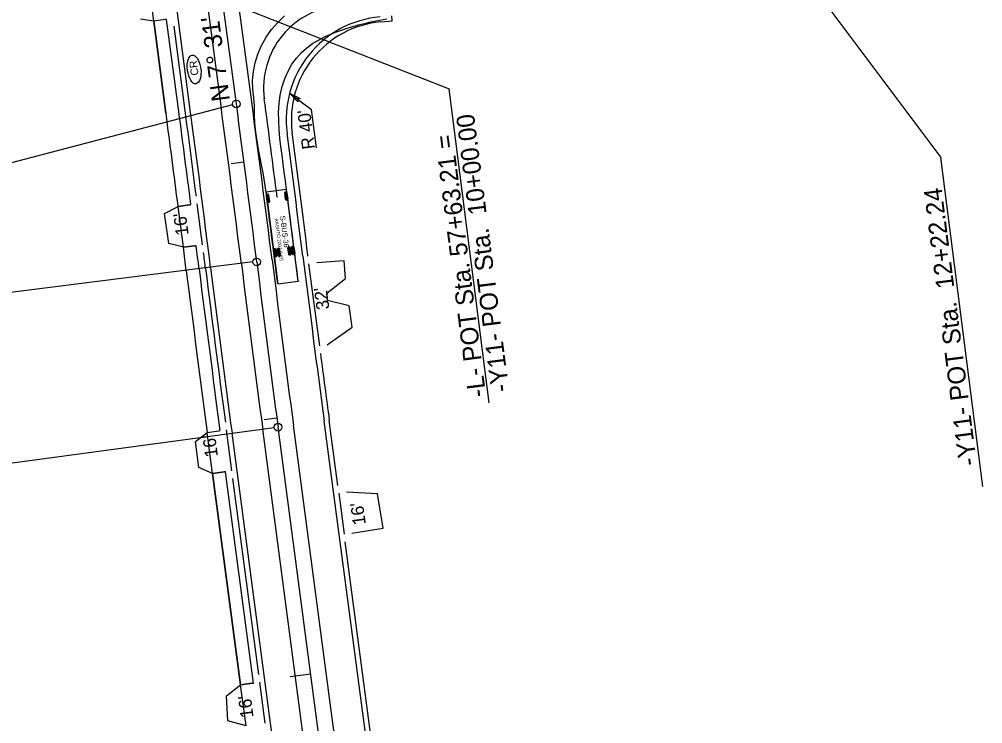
# Model space of a CAD drawing. Extents: x 2367848 to 2369479, y 800728 to 808616.
# Drawn here: x 2368547.1 to 2368920.4, y 805799.6 to 806072.5 of the extents above; entities that cross this region are included whole.
import ezdxf

# ---------------------------------------------------------------- set-up
doc = ezdxf.new("R2010")
doc.units = 0
for name, color, linetype in [('Prop AutoTurn Projected Path', 7, 'Continuous'), ('Prop AutoTurn Simulation', 7, 'Continuous'), ('Prop Conc 2ft 6in Curb and Gutter', 7, 'Continuous'), ('Prop Conc 4in Sidewalk', 7, 'Continuous'), ('Prop Conc Drive Radius Type', 7, 'Continuous'), ('Prop Conc Driveway', 7, 'Continuous'), ('Prop Dimension', 7, 'Continuous'), ('Prop EOT', 7, 'Continuous'), ('Prop Horizontal Alignment', 7, 'Continuous'), ('Prop Horizontal Alignment Direction Label', 7, 'Continuous'), ('Prop Horizontal Alignment Station Label', 7, 'Continuous'), ('Prop Horizontal Alignment Tick Large', 7, 'Continuous'), ('Prop Horizontal Alignment Tick Small', 7, 'Continuous'), ('Prop Lane Lines', 7, 'Continuous'), ('Prop Shade Light', 7, 'Continuous'), ('Prop Terminator CELL', 7, 'Continuous'), ('Prop WCC CELL', 7, 'Continuous'), ('Prop WCR CELL', 7, 'Continuous')]:
    doc.layers.add(name, color=color, linetype=linetype)

# ---------------------------------------------------------------- blocks, each defined once
blk = doc.blocks.new('CR')
at = {"layer": 'Prop WCC CELL'}
blk.add_ellipse((0.02, -0.02), major_axis=(5.61, 0), ratio=0.462467, dxfattribs=at)
blk.add_text('CR', height=3, dxfattribs=at).set_placement((-2.34, -1.5))

msp = doc.modelspace()

# ---------------------------------------------------------------- linework, layer by layer
at = {"layer": 'Prop AutoTurn Projected Path'}
for centre, radius, start, end in [((2368673.73, 806045.93), 32, 93.7494, 187.5296), ((2358717.33, 804729.9), 10011, 7.309596, 7.529629)]:
    msp.add_arc(centre, radius, start, end, dxfattribs=at)
at = {"layer": 'Prop AutoTurn Simulation'}
for p, q in [((2368650.62, 806006.6), (2368642.68, 806005.58)), ((2368642.68, 806005.58), (2368647.24, 805970.07)), ((2368642.68, 806005.58), (2368642.68, 806005.58)), ((2368642.99, 806004.78), (2368643.42, 806001.47)), ((2368643.2, 806004.81), (2368643.63, 806001.5)), ((2368643.41, 806004.83), (2368643.83, 806001.53)), ((2368650.1, 806005.69), (2368650.53, 806002.39)), ((2368650.31, 806005.72), (2368650.73, 806002.41)), ((2368650.52, 806005.75), (2368650.94, 806002.44)), ((2368655.17, 805971.09), (2368650.62, 806006.6)), ((2368645.7, 805983.65), (2368646.13, 805980.35)), ((2368645.91, 805983.68), (2368646.34, 805980.37)), ((2368646.12, 805983.71), (2368646.54, 805980.4)), ((2368647.19, 805983.84), (2368647.62, 805980.54)), ((2368647.4, 805983.87), (2368647.82, 805980.56)), ((2368647.61, 805983.9), (2368648.03, 805980.59)), ((2368651.33, 805984.37), (2368651.75, 805981.07)), ((2368651.53, 805984.4), (2368651.96, 805981.09)), ((2368651.74, 805984.43), (2368652.16, 805981.12)), ((2368652.81, 805984.57), (2368653.24, 805981.26)), ((2368653.02, 805984.59), (2368653.44, 805981.29)), ((2368653.23, 805984.62), (2368653.65, 805981.31)), ((2368647.24, 805970.07), (2368655.17, 805971.09))]:
    msp.add_line(p, q, dxfattribs=at)
for points in [[(2368647.24, 805970.07), (2368646.78, 805973.62), (2368646.33, 805977.17), (2368645.87, 805980.72), (2368645.41, 805984.28), (2368644.96, 805987.83), (2368644.5, 805991.38), (2368644.05, 805994.93), (2368643.59, 805998.48), (2368643.13, 806002.03), (2368642.67, 806005.58), (2368642.67, 806005.58), (2368642.24, 806008.89), (2368641.71, 806012.2), (2368641.1, 806015.49), (2368640.43, 806018.79), (2368639.78, 806022.11), (2368639.19, 806025.46), (2368638.71, 806028.82), (2368638.36, 806032.2), (2368638.18, 806035.54), (2368638.15, 806038.79), (2368637.93, 806042.04), (2368637.54, 806045.36), (2368637.48, 806048.76), (2368637.79, 806052.2), (2368638.48, 806055.64), (2368639.53, 806059.03), (2368640.95, 806062.33), (2368642.7, 806065.5), (2368644.79, 806068.5), (2368647.18, 806071.28), (2368649.86, 806073.83)], [(2368678.18, 806070.23), (2368679.08, 806070.47), (2368680.22, 806070.75), (2368681.41, 806071.04), (2368682.65, 806071.32), (2368683.93, 806071.6), (2368685.26, 806071.87), (2368686.62, 806072.15), (2368688.01, 806072.41), (2368689.43, 806072.67)], [(2368655.17, 805971.09), (2368654.72, 805974.64), (2368654.26, 805978.19), (2368653.81, 805981.74), (2368653.35, 805985.29), (2368652.9, 805988.84), (2368652.44, 805992.4), (2368651.99, 805995.95), (2368651.53, 805999.5), (2368651.07, 806003.05), (2368650.62, 806006.6), (2368650.62, 806006.6), (2368650.62, 806006.6), (2368650.19, 806009.91), (2368649.76, 806013.23), (2368649.34, 806016.55), (2368648.91, 806019.86), (2368648.47, 806023.18), (2368648.06, 806026.5), (2368647.75, 806029.82), (2368647.57, 806033.16), (2368647.55, 806036.51), (2368647.75, 806039.84), (2368648.2, 806043.15), (2368648.93, 806046.4), (2368649.93, 806049.5), (2368651.2, 806052.4), (2368652.73, 806055.07), (2368654.47, 806057.49), (2368656.41, 806059.63), (2368658.51, 806061.49), (2368660.73, 806063.09), (2368663.01, 806064.46), (2368665.32, 806065.66), (2368667.64, 806066.71), (2368669.95, 806067.64), (2368672.26, 806068.46), (2368674.55, 806069.2), (2368676.82, 806069.87), (2368678.18, 806070.23)]]:
    msp.add_lwpolyline(points, dxfattribs=at)
for points in [[(2368642.94, 806004.77), (2368643.46, 806004.84), (2368643.67, 806004.4), (2368643.98, 806002.02), (2368643.88, 806001.53), (2368643.37, 806001.47), (2368643.15, 806001.91), (2368642.85, 806004.29)], [(2368650.05, 806005.69), (2368650.57, 806005.75), (2368650.78, 806005.31), (2368651.09, 806002.93), (2368650.99, 806002.45), (2368650.48, 806002.38), (2368650.26, 806002.82), (2368649.96, 806005.2)], [(2368645.65, 805983.65), (2368646.17, 805983.71), (2368646.38, 805983.27), (2368646.69, 805980.89), (2368646.59, 805980.41), (2368646.08, 805980.34), (2368645.86, 805980.78), (2368645.56, 805983.16)], [(2368647.14, 805983.84), (2368647.66, 805983.9), (2368647.87, 805983.46), (2368648.18, 805981.08), (2368648.08, 805980.6), (2368647.57, 805980.53), (2368647.35, 805980.97), (2368647.05, 805983.35)], [(2368651.27, 805984.37), (2368651.79, 805984.43), (2368652, 805983.99), (2368652.31, 805981.61), (2368652.21, 805981.13), (2368651.7, 805981.06), (2368651.48, 805981.5), (2368651.18, 805983.89)], [(2368652.76, 805984.56), (2368653.28, 805984.62), (2368653.49, 805984.18), (2368653.8, 805981.8), (2368653.7, 805981.32), (2368653.19, 805981.25), (2368652.97, 805981.7), (2368652.67, 805984.08)]]:
    msp.add_lwpolyline(points, close=True, dxfattribs=at)
for centre in [(2368678.18, 806070.23), (2368678.18, 806070.23), (2368642, 806041.73), (2368642, 806041.73), (2368646.97, 806003.61), (2368655.17, 805971.09), (2368647.24, 805970.07)]:
    msp.add_circle(centre, 0.0417, dxfattribs=at)
at = {"layer": 'Prop Conc 2ft 6in Curb and Gutter'}
for p, q in [((2368687.09, 806071.46), (2368691.58, 806071.86)), ((2368691.58, 806071.86), (2368691.4, 806073.85)), ((2368611.35, 806037.09), (2368607.03, 806069.78)), ((2368670.51, 805891.85), (2368667.16, 805917.13)), ((2368639.85, 805818.64), (2368629.79, 805894.61)), ((2368758.08, 805230.44), (2368673.39, 805870.04))]:
    msp.add_line(p, q, dxfattribs=at)
for centre, radius, start, end in [((2368690.47, 806033.61), 38, 95.1122, 187.4476), ((2358717.33, 804729.9), 9980, 7.334525, 7.526261), ((2358717.33, 804729.9), 10020, 7.172685, 7.447577), ((2358717.33, 804729.9), 9980, 7.172685, 7.208222), ((2378560.81, 807227.11), 9980, 187.172674, 187.174058), ((2378560.81, 807227.11), 10020, 187.172674, 187.516225), ((2378560.81, 807227.11), 9980, 187.392226, 187.5424)]:
    msp.add_arc(centre, radius, start, end, dxfattribs=at)
at = {"layer": 'Prop Conc 4in Sidewalk'}
for p, q in [((2368603.91, 806036.11), (2368599.2, 806071.79)), ((2368608.87, 806036.76), (2368604.16, 806072.39)), ((2368632.81, 805814.69), (2368621.96, 805896.6)), ((2368637.76, 805815.38), (2368626.93, 805897.21))]:
    msp.add_line(p, q, dxfattribs=at)
for centre, radius, start, end in [((2368604.04, 806069.38), 3.01, 87.6915, 97.1618), ((2358717.33, 804729.9), 9972.5, 7.317252, 7.526261), ((2358717.33, 804729.9), 9977.5, 7.317563, 7.526261), ((2368612.65, 806003.58), 3, 277.4213, 287.6804), ((2358717.33, 804729.9), 9972.5, 7.172685, 7.225325), ((2368615.47, 805981.75), 3.01, 87.5484, 97.1646), ((2358717.33, 804729.9), 9977.5, 7.172685, 7.225151), ((2378560.81, 807227.11), 10027.5, 187.172674, 187.533386), ((2378560.81, 807227.11), 10022.5, 187.172674, 187.533139), ((2368623.93, 805916.03), 3, 277.5824, 287.1694), ((2368626.81, 805894.2), 3.01, 87.757, 97.321), ((2368636.87, 805818.25), 3, 277.5806, 287.1623)]:
    msp.add_arc(centre, radius, start, end, dxfattribs=at)
at = {"layer": 'Prop Conc Drive Radius Type'}
for p, q in [((2368618.07, 805985.13), (2368616.01, 806000.99)), ((2368659.18, 805977.77), (2368663.38, 805946.04)), ((2368629.4, 805897.58), (2368627.3, 805913.45)), ((2368670.9, 805888.88), (2368673, 805873.02)), ((2368642.35, 805799.81), (2368640.24, 805815.67))]:
    msp.add_line(p, q, dxfattribs=at)
at = {"layer": 'Prop Conc Driveway'}
for p, q in [((2368599.2, 806071.79), (2368597.15, 806087.66)), ((2368599.2, 806071.79), (2368594.06, 806072.59)), ((2368603.66, 806072.37), (2368599.2, 806071.79)), ((2368603.39, 805997.3), (2368608.58, 806000.03)), ((2368613.04, 806000.61), (2368608.58, 806000.03)), ((2368610.63, 805984.16), (2368608.58, 806000.03)), ((2368604.97, 805985.64), (2368603.39, 805997.3)), ((2368610.63, 805984.16), (2368604.97, 805985.64)), ((2368610.63, 805984.16), (2368615.1, 805984.74)), ((2368615.29, 805908.91), (2368619.86, 805912.46)), ((2368619.86, 805912.46), (2368624.32, 805913.05)), ((2368621.96, 805896.6), (2368619.86, 805912.46)), ((2368616.62, 805898.89), (2368615.29, 805908.91)), ((2368621.96, 805896.6), (2368616.62, 805898.89)), ((2368621.96, 805896.6), (2368626.42, 805897.19)), ((2368637.27, 805815.28), (2368632.81, 805814.69)), ((2368634.91, 805798.82), (2368632.81, 805814.69))]:
    msp.add_line(p, q, dxfattribs=at)
at = {"layer": 'Prop Dimension'}
for p in [(2368651.81, 806043.85), (2368662.24, 806022.67)]:
    msp.add_line(p, (2368660.31, 806037.55), dxfattribs=at)
at = {"layer": 'Prop EOT'}
for p, q in [((2368613.33, 806037.35), (2368557.45, 806460.31)), ((2368672.98, 805978.96), (2368662.3, 805978.13)), ((2368673.45, 805972.08), (2368672.98, 805978.96)), ((2368666.17, 805966.34), (2368673.45, 805972.08)), ((2368666.51, 805963.59), (2368666.17, 805966.34)), ((2368674.9, 805961.48), (2368666.51, 805963.59)), ((2368676.06, 805953.17), (2368674.9, 805961.48)), ((2368666.35, 805946.44), (2368676.06, 805953.17)), ((2368756.1, 805230.18), (2368665.18, 805916.87)), ((2368664.15, 805650.39), (2368629.49, 805912.14)), ((2368685.82, 805888.62), (2368673.87, 805889.27)), ((2368688.02, 805875.33), (2368685.82, 805888.62)), ((2368675.97, 805873.41), (2368688.02, 805875.33)), ((2368627.29, 805810.38), (2368632.81, 805814.69)), ((2368627.86, 805800.77), (2368627.29, 805810.38)), ((2368634.91, 805798.82), (2368627.86, 805800.77))]:
    msp.add_line(p, q, dxfattribs=at)
for centre, radius, start, end in [((2368690.47, 806033.61), 40, 95.1122, 187.4476), ((2358717.33, 804729.9), 9982, 7.172685, 7.526261), ((2358717.33, 804729.9), 10018, 7.172685, 7.447577), ((2378560.81, 807227.11), 9982, 187.172674, 187.5424), ((2378560.81, 807227.11), 10018, 187.172674, 187.5424)]:
    msp.add_arc(centre, radius, start, end, dxfattribs=at)
at = {"layer": 'Prop Horizontal Alignment'}
for p, q in [((2368631.17, 806039.71), (2368556.15, 806607.59)), ((2368753.14, 805115.37), (2368647.33, 805914.51))]:
    msp.add_line(p, q, dxfattribs=at)
for centre, start, end in [((2358717.33, 804729.9), 7.172685, 7.526261), ((2378560.81, 807227.11), 187.172674, 187.5424)]:
    msp.add_arc(centre, 10000, start, end, dxfattribs=at)
at = {"layer": 'Prop Horizontal Alignment Station Label'}
for p, q in [((2368847.64, 806094.4), (2368904.1, 806018.96)), ((2368625.87, 806079.87), (2368713.66, 806045.49)), ((2368729.19, 805923.89), (2368713.66, 806045.49)), ((2368629.72, 806039.33), (2368362.9, 805969.6)), ((2368920.38, 805891.52), (2368904.1, 806018.96)), ((2368637.57, 805978.51), (2368390.31, 805947.21)), ((2368645.82, 805914.28), (2368424.55, 805884.43))]:
    msp.add_line(p, q, dxfattribs=at)
for centre in [(2368631.17, 806039.71), (2368631.17, 806039.71), (2368639.07, 805978.51), (2368639.07, 805978.51), (2368647.33, 805914.51), (2368647.33, 805914.51)]:
    msp.add_circle(centre, 1.5, dxfattribs=at)
at = {"layer": 'Prop Horizontal Alignment Tick Large'}
msp.add_line((2368659.99, 805818.88), (2368652.06, 805817.83), dxfattribs=at)
msp.add_line((2368659.99, 805818.88), (2368652.06, 805817.83), dxfattribs=at)
at = {"layer": 'Prop Horizontal Alignment Tick Small'}
for p, q in [((2368634.12, 806017.2), (2368629.16, 806016.56)), ((2368634.12, 806017.2), (2368629.16, 806016.56)), ((2368646.87, 805918.02), (2368641.91, 805917.36)), ((2368646.87, 805918.02), (2368641.91, 805917.36))]:
    msp.add_line(p, q, dxfattribs=at)
at = {"layer": 'Prop Lane Lines'}
for p, q in [((2368625.23, 806038.92), (2368550.2, 806606.8)), ((2368637.12, 806040.49), (2368562.1, 806608.37)), ((2368759.09, 805116.16), (2368653.28, 805915.29)), ((2368747.19, 805114.58), (2368641.38, 805913.72))]:
    msp.add_line(p, q, dxfattribs=at)
for centre, radius, start, end in [((2358717.33, 804729.9), 9994, 7.172685, 7.526261), ((2358717.33, 804729.9), 10006, 7.172685, 7.526261), ((2378560.81, 807227.11), 10006, 187.172674, 187.5424), ((2378560.81, 807227.11), 9994, 187.172674, 187.5424)]:
    msp.add_arc(centre, radius, start, end, dxfattribs=at)
at = {"layer": 'Prop Shade Light'}
for p, q in [((2368603.66, 806072.37), (2368599.2, 806071.79)), ((2368599.2, 806071.79), (2368603.91, 806036.11)), ((2368608.87, 806036.76), (2368604.16, 806072.39)), ((2368608.61, 806000.03), (2368613.04, 806000.61)), ((2368615.1, 805984.74), (2368610.64, 805984.16)), ((2368619.86, 805912.46), (2368624.32, 805913.05)), ((2368626.42, 805897.19), (2368621.96, 805896.6)), ((2368621.96, 805896.6), (2368632.81, 805814.69)), ((2368637.76, 805815.38), (2368626.93, 805897.21)), ((2368632.81, 805814.69), (2368637.27, 805815.28))]:
    msp.add_line(p, q, dxfattribs=at)
for centre, radius, start, end in [((2368604.04, 806069.38), 3.01, 87.6915, 97.1618), ((2358717.33, 804729.9), 9972.5, 7.317252, 7.526261), ((2358717.33, 804729.9), 9977.5, 7.317563, 7.526261), ((2368612.65, 806003.58), 3, 277.4213, 287.6804), ((2358717.33, 804729.9), 9972.5, 7.172685, 7.225325), ((2368615.47, 805981.75), 3.01, 87.5484, 97.1646), ((2358717.33, 804729.9), 9977.5, 7.172685, 7.225151), ((2378560.81, 807227.11), 10027.5, 187.172674, 187.533386), ((2378560.81, 807227.11), 10022.5, 187.172674, 187.533139), ((2368623.93, 805916.03), 3, 277.5824, 287.1694), ((2368626.81, 805894.2), 3.01, 87.757, 97.321), ((2368636.87, 805818.25), 3, 277.5806, 287.1623)]:
    msp.add_arc(centre, radius, start, end, dxfattribs=at)
at = {"layer": 'Prop Terminator CELL'}
msp.add_lwpolyline([(2368654.96, 806040.55), (2368651.81, 806043.85), (2368655.92, 806041.8), (2368654.98, 806041.5)], close=True, dxfattribs=at)

# ---------------------------------------------------------------- block references
at = {"layer": 'Prop WCR CELL', "rotation": 97.54241161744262}
msp.add_blockref('CR', (2368614.79, 806053.04), dxfattribs=at)

# ---------------------------------------------------------------- texts
at = {"layer": 'Prop AutoTurn Simulation'}
for s, height, p in [('S-BUS-36', 2, (2368648.07, 805996.29)), ('AASHTO 2001 (US)', 1.3333, (2368646.02, 805995.24)), ('(c) 2014 Transoft Solutions, Inc. All rights reserved.', 0.08, (2368648.68, 805989.95))]:
    msp.add_text(s, height=height, rotation=277.3096, dxfattribs=at).set_placement(p)
at = {"layer": 'Prop Dimension'}
for s, rotation, p in [("R 40'", 97.3931, (2368661.69, 806022.44)), ("16'", 97.2516, (2368612.72, 805989.04)), ("32'", 97.3431, (2368667.27, 805960.3)), ("16'", 97.5424, (2368624.06, 805903.2)), ("16'", 97.5424, (2368681.36, 805876.91)), ("16'", 97.5424, (2368637.87, 805802.18))]:
    msp.add_text(s, height=5, rotation=rotation, dxfattribs=at).set_placement(p)
at = {"layer": 'Prop Horizontal Alignment Direction Label'}
msp.add_text('N 7%%d 31\' 34.5"   W', height=7, rotation=97.5263, dxfattribs=at).set_placement((2368628.69, 806041.13))
at = {"layer": 'Prop Horizontal Alignment Station Label'}
for s, p in [('-Y11- POT Sta.  10+00.00', (2368736.95, 805928.52)), ('-L- POT Sta. 57+63.21 =', (2368727.99, 805926.49)), ('-Y11- POT Sta.  12+22.24', (2368918.17, 805899.96))]:
    msp.add_text(s, height=7, rotation=97.2784, dxfattribs=at).set_placement(p)

doc.saveas('drawing.dxf')
